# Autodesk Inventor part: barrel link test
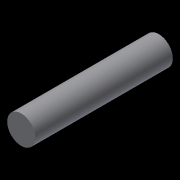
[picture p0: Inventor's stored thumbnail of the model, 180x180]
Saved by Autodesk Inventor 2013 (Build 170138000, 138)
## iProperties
Created: 2013-01
Part Number: barrel link test
Material: Generic
Document SubType Name: Modeling
Designer: John
Density: 1 g/cm^3
Author: John
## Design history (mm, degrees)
sketch "Sketch1"
  geometry: C1 r 2.603 at (0, 0); 1 further point
  constraints: 1 centre point, 1 coincident
  dimensions: "d0" = 5.207 diameter of C1
extrude "Extrusion1" new body sketch "Sketch1" distance "d1" = 25.4; taper "d2" = 0 deg
body "Solid1"
